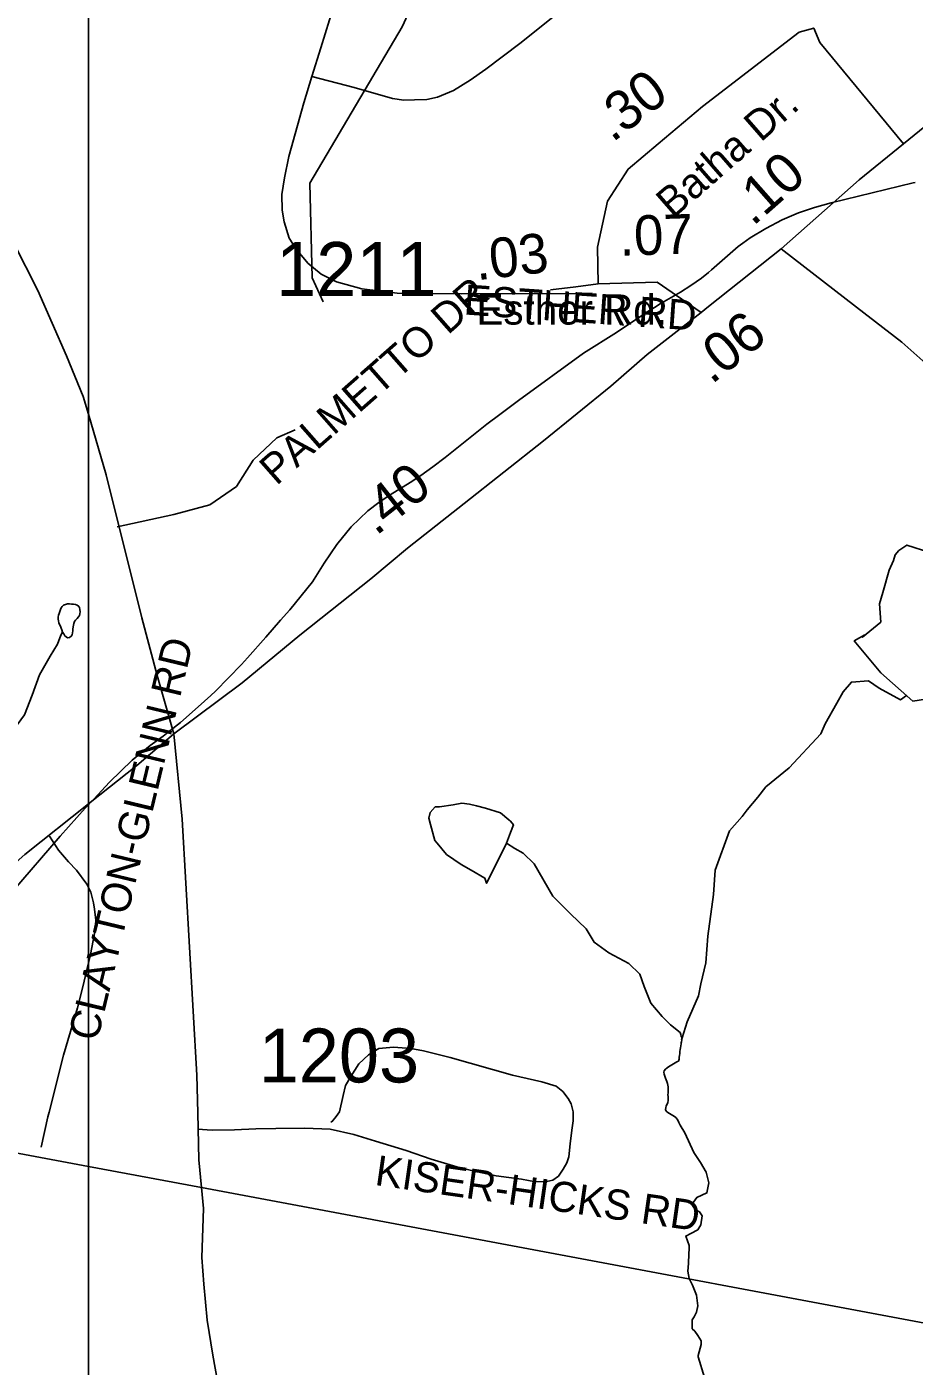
# Model space of a CAD drawing. Extents: x 1950930 to 2061844, y 904556 to 1017002.
# Drawn here: x 1990077 to 1992875, y 948596 to 952820 of the extents above; entities that cross this region are included whole.
import ezdxf

# ---------------------------------------------------------------- set-up
doc = ezdxf.new("R2010")
doc.units = 0
for name, color, linetype in [('Exist Hydrographic Creek Single Shore', 7, 'Continuous'), ('Exist Hydrographic Misc Water Feature', 7, 'Continuous'), ('Exist Hydrographic Pond Over 1500 Sq Ft', 7, 'Continuous'), ('Exist Road Non-System Type 51', 7, 'Continuous'), ('Exist Road Non-System Type 51 Label', 7, 'Continuous'), ('Exist Road Primary NC Attributed', 7, 'Continuous'), ('Exist Road Primary NC Mileage Hundredths English Label', 7, 'Continuous'), ('Exist Road Primary US Structure Standard Bridge CELL', 7, 'Continuous'), ('Exist Road Secondary Type 51 Attributed', 7, 'Continuous'), ('Exist Road Secondary Type 51 Label', 7, 'Continuous'), ('Exist Road Secondary Type 51 Number Label', 7, 'Continuous'), ('Exist Utilities Electrical Transmission Line', 7, 'Continuous'), ('Map Preparation Inset Cut Line', 7, 'Continuous')]:
    doc.layers.add(name, color=color, linetype=linetype)

msp = doc.modelspace()

# ---------------------------------------------------------------- linework, layer by layer
at = {"layer": 'Exist Hydrographic Creek Single Shore'}
for points in [[(1992850.4, 950711.2), (1992831, 950697.8), (1992764.2, 950734.2), (1992730.2, 950757.3), (1992676.7, 950753.8), (1992650.6, 950722.9), (1992631.1, 950687.3), (1992593.6, 950622.3), (1992579.7, 950590.7), (1992480.8, 950483.7), (1992407, 950423.8), (1992381.2, 950391.2), (1992347.8, 950350.8), (1992331.8, 950329.3), (1992292.2, 950285), (1992247.1, 950160.3), (1992241.8, 950084), (1992224.3, 949952.4), (1992217.6, 949868.1), (1992202, 949802), (1992194.4, 949764.1), (1992158.9, 949682.2), (1992143.3, 949631.5), (1992141.3, 949624.1)], [(1991588.7, 950245.4), (1991615.7, 950229.2), (1991641.6, 950213.8), (1991676, 950180.2), (1991734.7, 950078.4), (1991791.3, 950023), (1991839.8, 949975.1), (1991865.9, 949933.4), (1991912.2, 949900), (1991974.8, 949866.6), (1992009, 949832.9), (1992023.2, 949793.4), (1992043.9, 949741.2), (1992080.4, 949699.4), (1992106, 949673.2), (1992136.4, 949648), (1992138.4, 949642.3), (1992139.8, 949636.4), (1992143.3, 949631.5), (1992141.3, 949624.1)], [(1992139.8, 949617.8), (1992139.4, 949613), (1992143.3, 949631.5), (1992137.8, 949600.6), (1992136.8, 949594.7), (1992136.1, 949588.3), (1992135.5, 949582.3), (1992134.9, 949575.9), (1992133.9, 949570.4), (1992133.1, 949564.4), (1992131.2, 949558.6), (1992126.5, 949555.7), (1992120.6, 949553.3), (1992115.2, 949550.1), (1992110.1, 949546.8), (1992105, 949543.9), (1992099.6, 949540.6), (1992095.3, 949537.2), (1992090.2, 949532.7), (1992086.5, 949527.7), (1992085.3, 949523), (1992086.1, 949517.2), (1992088, 949510.4), (1992090, 949504.8), (1992092.3, 949498.8), (1992094.5, 949494), (1992096.8, 949487.9), (1992098, 949482.5), (1992098.8, 949476.7), (1992098.6, 949470.2), (1992098.4, 949464.1), (1992098.4, 949458.5), (1992098.2, 949452), (1992098.4, 949446.3), (1992098.8, 949440.6), (1992098.6, 949434.1), (1992097.6, 949428.2), (1992095.3, 949422.4), (1992092.7, 949416.8), (1992091.2, 949411.2), (1992090.8, 949405.3), (1992092.9, 949400.5), (1992098.2, 949396.4), (1992103.5, 949392.8), (1992108.1, 949389.6), (1992113.6, 949386.7), (1992118.9, 949383.5), (1992123.4, 949380), (1992127.3, 949375.4), (1992130, 949370), (1992132.9, 949364.4), (1992136.6, 949356.1), (1992151.5, 949331.9), (1992180, 949270), (1992200.5, 949238.4), (1992218.6, 949208.4), (1992227, 949174.7), (1992221.2, 949142.7), (1992189.1, 949128.5), (1992173.5, 949105.7), (1992183.5, 949090), (1992198.1, 949082.5), (1992205.9, 949070.8), (1992202, 949042.1), (1992191.9, 949025.8), (1992170, 949014.2), (1992154.4, 949006.4), (1992164.7, 948976.4), (1992164.7, 948965.9), (1992164.4, 948950), (1992162.8, 948919.8), (1992161, 948896.2), (1992165.1, 948872.4), (1992175.3, 948852.2), (1992187.8, 948820.3), (1992191.9, 948786.3), (1992188.2, 948766.6), (1992180.4, 948752), (1992174.5, 948742.4), (1992174.3, 948726.1), (1992174.5, 948714.3), (1992182.5, 948706.2), (1992192.5, 948692.8), (1992203, 948676.3), (1992203.2, 948664.5), (1992193.2, 948630.3), (1992193.4, 948626.2), (1992213.9, 948560.2)]]:
    msp.add_lwpolyline(points, dxfattribs=at)
at = {"layer": 'Exist Hydrographic Misc Water Feature'}
for p, q in [((1992871.7, 952327.7), (1992877.4, 952329.2)), ((1990977.6, 951069.3), (1991014.7, 951129.1)), ((1990977.6, 951069.3), (1991014.7, 951129.1)), ((1990506.6, 950583.2), (1990527.5, 950599.8)), ((1990031.7, 950093.1), (1990181.6, 950267.4))]:
    msp.add_line(p, q, dxfattribs=at)
for points in [[(1991010.6, 951952.4), (1990976.7, 952028.6), (1990968.7, 952327.5), (1991260.7, 952820.2), (1992128.7, 954712.4), (1992220.6, 955360.3), (1992261.3, 955474)], [(1992406.8, 952184.5), (1992458.5, 952211.9), (1992509.8, 952233.4), (1992560.4, 952250), (1992612.7, 952264.7), (1992871.7, 952327.7)], [(1992406.8, 952184.5), (1992458.5, 952211.9), (1992509.8, 952233.4), (1992560.4, 952250), (1992612.7, 952264.7), (1992871.7, 952327.7)], [(1992334.4, 952138.1), (1992357.6, 952155), (1992406.8, 952184.5)], [(1992334.4, 952138.1), (1992357.6, 952155), (1992406.8, 952184.5)], [(1992226, 952045.6), (1992235.6, 952053.5), (1992319.7, 952127.3), (1992334.4, 952138.1)], [(1992226, 952045.6), (1992235.6, 952053.5), (1992319.7, 952127.3), (1992334.4, 952138.1)], [(1992100.5, 951962.1), (1992137.6, 951983.7), (1992170.6, 952004.2), (1992203.6, 952027.2), (1992226, 952045.6)], [(1992100.5, 951962.1), (1992137.6, 951983.7), (1992170.6, 952004.2), (1992203.6, 952027.2), (1992226, 952045.6)], [(1992057.4, 951936.5), (1992071.6, 951945.3), (1992100.5, 951962.1)], [(1992057.4, 951936.5), (1992071.6, 951945.3), (1992100.5, 951962.1)], [(1991567.9, 951597.5), (1991626.6, 951642), (1991831.6, 951791.4), (1991935.6, 951856.5), (1992040.6, 951926), (1992057.4, 951936.5)], [(1991567.9, 951597.5), (1991626.6, 951642), (1991831.6, 951791.4), (1991935.6, 951856.5), (1992040.6, 951926), (1992057.4, 951936.5)], [(1991357, 951432.5), (1991395.9, 951462.4), (1991527.6, 951567), (1991567.9, 951597.5)], [(1991357, 951432.5), (1991395.9, 951462.4), (1991527.6, 951567), (1991567.9, 951597.5)], [(1991099.6, 951243.4), (1991151.7, 951293.4), (1991186.8, 951320.1), (1991222.6, 951344.2), (1991285.6, 951383.3), (1991318.8, 951405.1), (1991357, 951432.5)], [(1991099.6, 951243.4), (1991151.7, 951293.4), (1991186.8, 951320.1), (1991222.6, 951344.2), (1991285.6, 951383.3), (1991318.8, 951405.1), (1991357, 951432.5)], [(1991014.7, 951129.1), (1991053.7, 951187), (1991099.6, 951243.4)], [(1991014.7, 951129.1), (1991053.7, 951187), (1991099.6, 951243.4)], [(1990876.9, 950948.7), (1990905.6, 950982), (1990977.6, 951069.3)], [(1990876.9, 950948.7), (1990905.6, 950982), (1990977.6, 951069.3)], [(1990189.4, 950910.9), (1990193.1, 950905.9), (1990197, 950900), (1990200.9, 950895.9), (1990205.4, 950893.4), (1990211.3, 950894.1), (1990217.1, 950898), (1990219.3, 950902.9), (1990220.8, 950908.6), (1990221.6, 950915.2), (1990222, 950920.8), (1990222.8, 950927.4), (1990223.6, 950933.1), (1990224.9, 950938.9), (1990227.3, 950944.5), (1990230.8, 950949.4), (1990235.5, 950954.3), (1990239.6, 950959.1), (1990242.5, 950963.1), (1990244.1, 950968.8), (1990244.7, 950975.4), (1990244.1, 950982.9), (1990242.7, 950988.6), (1990239.8, 950993.5), (1990235.7, 950996.1), (1990230.4, 950997.8), (1990224, 950998.9), (1990217.5, 950999.8), (1990210.9, 950999.9), (1990204.6, 951000), (1990198.6, 950998.5), (1990192.5, 950996.2), (1990187.9, 950992.1), (1990185.3, 950987.3), (1990182.6, 950982.5), (1990180.4, 950975.9), (1990178.3, 950970.1), (1990177.1, 950964.5), (1990176.1, 950957.9), (1990175.6, 950952.2), (1990176.3, 950946.5), (1990177.9, 950940.7), (1990180, 950934.9), (1990182.6, 950930), (1990184.9, 950924.1), (1990187.3, 950918.3), (1990189.4, 950910.9)], [(1990772.8, 950830.6), (1990830.6, 950895.1), (1990876.9, 950948.7)], [(1990772.8, 950830.6), (1990830.6, 950895.1), (1990876.9, 950948.7)], [(1989911.1, 950577), (1989924.5, 950587.3), (1990020.2, 950607.5), (1990046.3, 950618.5), (1990069.8, 950650), (1990093.4, 950712.7), (1990117, 950777), (1990150.2, 950835.4), (1990174, 950873.5), (1990183.8, 950901.1), (1990189.4, 950910.9)], [(1990656.9, 950711.7), (1990671.7, 950725.4), (1990753.7, 950809.5), (1990772.8, 950830.6)], [(1990656.9, 950711.7), (1990671.7, 950725.4), (1990753.7, 950809.5), (1990772.8, 950830.6)], [(1990527.5, 950599.8), (1990560.9, 950626.2), (1990617.5, 950675.6), (1990656.9, 950711.7)], [(1990527.5, 950599.8), (1990560.9, 950626.2), (1990617.5, 950675.6), (1990656.9, 950711.7)], [(1990288, 950384.9), (1990337.6, 950438.4), (1990408.6, 950507.2), (1990465.4, 950553.4), (1990506.6, 950583.2)], [(1990288, 950384.9), (1990337.6, 950438.4), (1990408.6, 950507.2), (1990465.4, 950553.4), (1990506.6, 950583.2)], [(1990181.6, 950267.4), (1990260.7, 950355.6), (1990288, 950384.9)], [(1990181.6, 950267.4), (1990260.7, 950355.6), (1990288, 950384.9)], [(1991588.7, 950245.4), (1991601.4, 950278.8), (1991611.2, 950303.7), (1991601.4, 950314.5), (1991596.9, 950319.7), (1991570.6, 950341.6), (1991522.4, 950355.7), (1991494.3, 950362.9), (1991472.4, 950369), (1991448.6, 950371.4), (1991420.7, 950366.8), (1991378.3, 950360.2), (1991364.7, 950359.8), (1991348.5, 950342), (1991344.6, 950324.3), (1991349, 950304.2), (1991363.7, 950254.1), (1991370.7, 950245.7), (1991399.6, 950210.4), (1991445.7, 950178.6), (1991478.1, 950160.8), (1991520.6, 950135.3), (1991526.5, 950119.3), (1991583.3, 950231.7), (1991588.7, 950245.4)]]:
    msp.add_lwpolyline(points, dxfattribs=at)
at = {"layer": 'Exist Hydrographic Pond Over 1500 Sq Ft'}
for points in [[(1992769.1, 950782.8), (1992685.3, 950883.5), (1992719.1, 950902.2), (1992711.8, 950895.2), (1992769.1, 950943), (1992765.4, 951000), (1992775.2, 951036.5), (1992795.8, 951106.8), (1992809.1, 951137.2), (1992814.2, 951154.8), (1992825.9, 951168.4), (1992851.8, 951185.8), (1992923.5, 951162.3)], [(1992909.8, 950699.7), (1992870, 950693.9), (1992769.1, 950782.8)]]:
    msp.add_lwpolyline(points, dxfattribs=at)
at = {"layer": 'Exist Road Non-System Type 51'}
for points in [[(1990975.4, 952663.7), (1991109.1, 952628.8), (1991229.5, 952593.6), (1991265.9, 952589), (1991299.4, 952589.5), (1991338.2, 952591.1), (1991372.1, 952598.1), (1991422, 952619.6), (1991474.6, 952651.5), (1991524.1, 952686.4), (1991631.1, 952767.6), (1991746.2, 952858.9), (1991882, 952971.4), (1991998.5, 953075.1), (1992043.5, 953114.8), (1992078.4, 953157.8)], [(1990975.4, 952663.7), (1991003.4, 952753.9), (1991045.1, 952886.3), (1991062.5, 952962.2), (1991067.8, 953014.9)], [(1991859.4, 951980), (1991806.8, 951978.6), (1991446.4, 951978.2), (1991244.9, 951979.8), (1991132.6, 951994), (1991053.1, 952016.4), (1991004.8, 952039.7), (1990963.2, 952075), (1990926.8, 952117.8), (1990903.8, 952153.2), (1990888.6, 952204.6), (1990882, 952241.4), (1990880.4, 952291.7), (1990889.6, 952343.6), (1990902.8, 952410.7), (1990949.8, 952580.6), (1990975.4, 952663.7)], [(1990362, 951242.8), (1990539.8, 951282.3), (1990654.1, 951313.1), (1990737.6, 951370.2), (1990790.4, 951453.8), (1990865.1, 951524.1), (1990922.8, 951549.4)], [(1990148.4, 950268.2), (1990177, 950223.4), (1990208, 950187.2), (1990233.4, 950160.8), (1990265.5, 950116.5), (1990278.8, 950090.7), (1990286.8, 950057.4), (1990290.2, 950037.8), (1990294.2, 950003.1), (1990291.9, 949971.5), (1990286.1, 949938.2), (1990277.5, 949894.5), (1990252.2, 949788), (1990236.2, 949726.5), (1990192.5, 949576.9), (1990147.1, 949397.4), (1990142.9, 949382.6), (1990121.8, 949286.5)], [(1990614.5, 949343.7), (1990660.9, 949340.4), (1990731.8, 949341.4), (1990798.8, 949344.3), (1990861.9, 949346.2), (1990952.8, 949347.1), (1991033.1, 949343.3), (1991107.9, 949327.1), (1991175.8, 949306), (1991272.4, 949276.3), (1991351.9, 949248.6), (1991432.2, 949224.7), (1991483, 949211.8), (1991556.6, 949196.4), (1991636, 949185.9), (1991680.1, 949177.3), (1991716.4, 949178.2), (1991735.6, 949183.1), (1991752.8, 949195.5), (1991768.1, 949217.5), (1991779.6, 949237.6), (1991785.4, 949256.8), (1991790.1, 949297.9), (1991794.9, 949340), (1991798.8, 949369.6), (1991798.8, 949398.4), (1991793, 949423.2), (1991783.4, 949440.4), (1991767.1, 949462.4), (1991746.1, 949478.8), (1991700.1, 949493.1), (1991608.2, 949514.1), (1991411.1, 949569.2), (1991327, 949590.2), (1991287.8, 949597.9), (1991233.1, 949602.7), (1991186.2, 949597.9), (1991153.8, 949577.8), (1991123.1, 949550), (1991098.2, 949509.8), (1991082, 949481.1), (1991074.4, 949449.6), (1991062.9, 949398.8), (1991052.4, 949383.5), (1991038, 949367.2), (1991035.1, 949366.3)]]:
    msp.add_lwpolyline(points, dxfattribs=at)
at = {"layer": 'Exist Road Primary NC Attributed'}
for points in [[(1992841.2, 952451.1), (1992986.9, 952569.4), (1993280.6, 952807.2), (1993461.7, 952953.6), (1993544, 953021)], [(1992454.7, 952120.2), (1992701.1, 952337.5), (1992841.2, 952451.1)], [(1992202.6, 951919.6), (1992226.3, 951938.2), (1992454.7, 952120.2)], [(1990540.5, 950589.9), (1990755.4, 950751.7), (1990937.5, 950901.6), (1991161.6, 951079.3), (1991276.6, 951176.3), (1991455.8, 951317), (1991706.1, 951514.8), (1991918.2, 951686.6), (1992033.1, 951786.6), (1992202.6, 951919.6)], [(1987869.8, 948144.4), (1987989.3, 948250.6), (1988287.5, 948542.4), (1988579.9, 948824), (1988783.1, 949023.1), (1989116.2, 949337.5), (1989210.4, 949426.9), (1989318.3, 949529.3), (1989564.6, 949759), (1989826.8, 949994.7), (1990070.9, 950210.4), (1990270.8, 950369.2), (1990277, 950374.2), (1990423.2, 950490.1), (1990510.3, 950564.1), (1990540.5, 950589.9)]]:
    msp.add_lwpolyline(points, dxfattribs=at)
at = {"layer": 'Exist Road Secondary Type 51 Attributed'}
for points in [[(1990540.5, 950589.9), (1990488, 950774.2), (1990439.3, 950956.6), (1990326.6, 951407.3), (1990270.8, 951598.6), (1990254.6, 951653.9), (1990201.6, 951782.4), (1990111.1, 951988.9), (1990034.4, 952139.7), (1989978.8, 952291.2), (1989893.7, 952512.5), (1989795.5, 952693.8), (1989783.1, 952709.3), (1989759.4, 952744.3), (1989736.8, 952766.9), (1989703.2, 952786), (1989675.5, 952802.2), (1989644.7, 952819.2), (1989599.7, 952834.9)], [(1992841.2, 952451.1), (1992577.5, 952771), (1992557.9, 952816.2), (1992512, 952803.4), (1992207.4, 952569.3), (1992067.5, 952451.5), (1991972.7, 952371.7), (1991908, 952270.8), (1991876.5, 952124.8), (1991878, 952009.2)], [(1992454.7, 952120.2), (1992693.1, 951935.7), (1992836, 951825.8), (1992911.2, 951758.1)], [(1991878, 952009.2), (1991807.3, 952000.2), (1991727.5, 951990.8)], [(1992202.6, 951919.6), (1992064.5, 952015.2), (1991878, 952009.2)], [(1990813, 948027.3), (1990808.6, 948121.2), (1990769.5, 948271.8), (1990739.4, 948362.1), (1990704.1, 948453.2), (1990680, 948537.5), (1990663.5, 948630.9), (1990645.5, 948741.5), (1990635, 948854.4), (1990629, 948938.7), (1990633.5, 949093.8), (1990627.4, 949159.3), (1990619.2, 949246.6), (1990616.2, 949395.7), (1990612.4, 949513.9), (1990566.6, 950321.6), (1990540.5, 950589.9)]]:
    msp.add_lwpolyline(points, dxfattribs=at)
at = {"layer": 'Exist Utilities Electrical Transmission Line'}
msp.add_line((1990627.4, 949159.3), (1990270.8, 949226.1), dxfattribs=at)
for points in [[(1990270.8, 949226.1), (1989217.3, 949423.5), (1989210.4, 949426.9)], [(1994614.4, 948515.4), (1994386.2, 948511.7), (1994144.3, 948556.2), (1993854.5, 948554.7), (1990627.4, 949159.3)]]:
    msp.add_lwpolyline(points, dxfattribs=at)
at = {"layer": 'Map Preparation Inset Cut Line'}
for p, q in [((1990270.8, 951598.6), (1990270.8, 955212.8)), ((1990270.8, 950559.1), (1990270.8, 951598.6)), ((1990270.8, 950369.2), (1990270.8, 950559.1)), ((1990270.8, 949226.1), (1990270.8, 950369.2)), ((1990270.8, 946671.5), (1990270.8, 949226.1))]:
    msp.add_line(p, q, dxfattribs=at)

# ---------------------------------------------------------------- texts
at = {"layer": 'Exist Road Non-System Type 51 Label'}
for s, rotation, p in [('  PALMETTO DR', 41.3418, (1990810.6, 951324.2)), ('  ESTHER RD', 356.0024, (1991382, 951918.1)), ('  CLAYTON-GLENN RD', 76.5006, (1990282.6, 949548.7)), ('  KISER-HICKS RD', 351.8408, (1991101.2, 949178))]:
    msp.add_text(s, height=95, rotation=rotation, dxfattribs=at).set_placement(p)
at = {"layer": 'Exist Road Primary NC Mileage Hundredths English Label'}
for s, rotation, p in [('.10', 41.4008, (1992365.7, 952188.8)), ('.06', 38.5511, (1992235.4, 951690.4)), ('.40', 38.1509, (1991177.5, 951212.8))]:
    msp.add_text(s, height=125, rotation=rotation, dxfattribs=at).set_placement(p)
at = {"layer": 'Exist Road Primary US Structure Standard Bridge CELL'}
for s, rotation, p in [('.30', 37.5446, (1991922.8, 952453.4)), ('.07', 1.8493, (1991946.5, 952098)), ('.03', 6.712, (1991495.8, 952020.6))]:
    msp.add_text(s, height=125, rotation=rotation, dxfattribs=at).set_placement(p)
at = {"layer": 'Exist Road Secondary Type 51 Label'}
msp.add_text('Batha Dr.', height=95, rotation=41.1029, dxfattribs=at).set_placement((1992113.7, 952212.7))
msp.add_text('Esther Rd.', height=95, dxfattribs=at).set_placement((1991494.6, 951881))
at = {"layer": 'Exist Road Secondary Type 51 Number Label'}
for s, p in [('1211', (1990862.8, 951971.3)), ('1203', (1990807.9, 949491))]:
    msp.add_text(s, height=170, dxfattribs=at).set_placement(p)

doc.saveas('drawing.dxf')
